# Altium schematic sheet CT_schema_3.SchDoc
size 257 x 245 mm
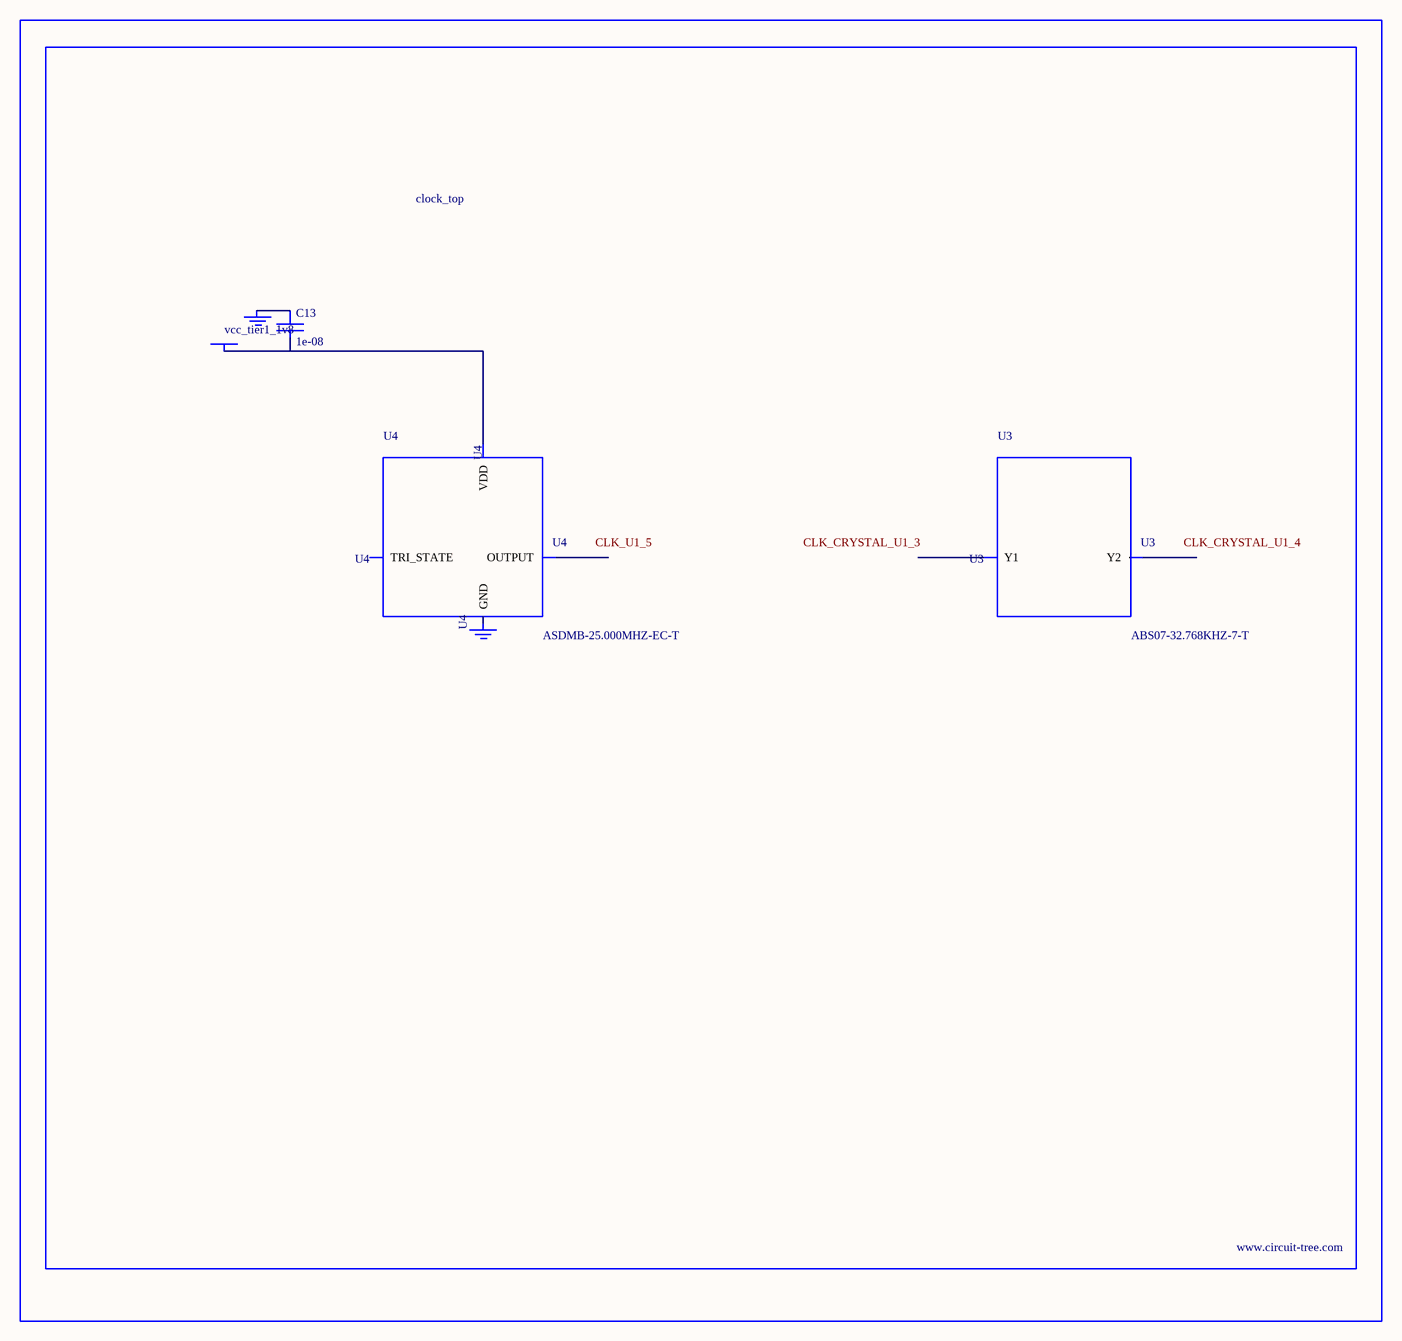
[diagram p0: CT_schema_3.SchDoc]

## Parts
BORDER2  (no value)
C13  1e-08  [C0402]
GND_INSTANCE_2_0  (no value)
GND_INSTANCE_2_1  (no value)
POWER_INSTANCE_2_0  vcc_tier1_1v8
U3  ABS07-32.768KHZ-7-T  [ABS07-32.768KHZ-7-T]
U4  ASDMB-25.000MHZ-EC-T  [ASDMB-XX.XXXXMHZ-XX-XX-XXX]

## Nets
NetC13_1: C13.1 GND_INSTANCE_2_0.0(GND)
NetC13_2: C13.2 POWER_INSTANCE_2_0.0(PWR) U4.4(VDD)

Not connected (* = marked no-connect by the designer): GND_INSTANCE_2_1 0(GND); U3 1(Y1) 2(Y2); U4 1(TRI_STATE) 2(GND) 3(OUTPUT)

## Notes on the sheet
- Labels drawn without touching a wire or pin: CLK_CRYSTAL_U1_3, CLK_CRYSTAL_U1_4, CLK_U1_5

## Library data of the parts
BORDER2 = BORDER_PAGE2
C13 = C0402C103K3RAC
GND_INSTANCE_2_0 GND_INSTANCE_2_1 = GND
POWER_INSTANCE_2_0 = PWR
